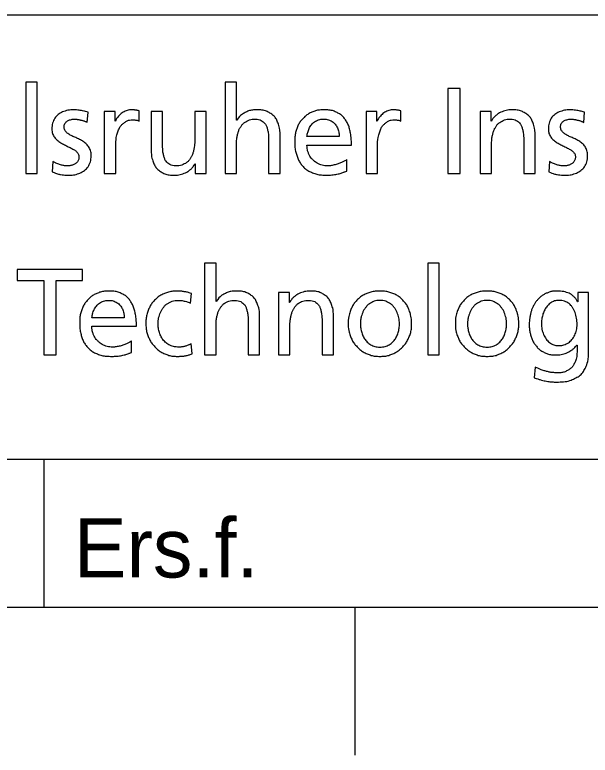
# Model space of a CAD drawing. Extents: x 0 to 395, y 0 to 270.
# Drawn here: x 136.01 to 155.45, y 0 to 25 of the extents above; entities that cross this region are included whole.
import ezdxf

# ---------------------------------------------------------------- set-up
doc = ezdxf.new("R2010")
doc.units = 0
doc.layers.add('90_Plankopf', color=7, linetype='Continuous')

msp = doc.modelspace()

# ---------------------------------------------------------------- linework, layer by layer
at = {"layer": '90_Plankopf'}
for p, q in [((5, 25), (390, 25)), ((140.21, 21.414), (140.21, 21.761)), ((149.056, 21.414), (149.056, 21.761)), ((138.456, 21.369), (138.489, 21.708)), ((155.231, 21.369), (155.264, 21.708)), ((146.971, 20.89), (145.882, 20.89)), ((145.882, 20.602), (147.384, 20.602)), ((137.296, 20.048), (137.276, 19.702)), ((147.223, 19.723), (147.223, 20.11)), ((154.071, 20.048), (154.051, 19.702)), ((141.95, 15.266), (141.983, 15.588)), ((139.705, 14.771), (138.615, 14.771)), ((138.615, 14.482), (140.118, 14.482)), ((139.957, 13.603), (139.957, 13.991)), ((142, 13.553), (141.971, 13.9)), ((153.595, 13.104), (153.554, 12.745)), ((100, 10), (225, 10)), ((137, 5), (137, 10)), ((5, 5), (390, 5)), ((147.5, 5), (147.5, 0))]:
    msp.add_line(p, q, dxfattribs=at)
for points in [[(136.38, 19.636), (136.767, 19.636), (136.767, 22.731), (136.38, 22.731), (136.38, 19.636)], [(143.508, 21.439), (143.5, 21.439), (143.5, 22.731), (143.112, 22.731), (143.112, 19.636), (143.5, 19.636), (143.5, 20.61)], [(150.645, 19.636), (151.058, 19.636), (151.058, 22.516), (150.645, 22.516), (150.645, 19.636)], [(139.406, 21.414), (139.397, 21.414), (139.397, 21.74), (139.034, 21.74), (139.034, 19.636), (139.422, 19.636), (139.422, 20.593)], [(141.003, 20.651), (141.003, 21.74), (140.615, 21.74), (140.615, 20.49)], [(142.092, 19.97), (142.101, 19.97), (142.101, 19.636), (142.476, 19.636), (142.476, 21.74), (142.088, 21.74), (142.088, 20.766)], [(148.251, 21.414), (148.243, 21.414), (148.243, 21.74), (147.88, 21.74), (147.88, 19.636), (148.268, 19.636), (148.268, 20.593)], [(152.115, 21.406), (152.107, 21.406), (152.107, 21.74), (151.731, 21.74), (151.731, 19.636), (152.119, 19.636), (152.119, 20.61)], [(144.586, 20.725), (144.586, 19.636), (144.973, 19.636), (144.973, 20.886)], [(153.204, 20.725), (153.204, 19.636), (153.592, 19.636), (153.592, 20.886)], [(142.817, 15.32), (142.809, 15.32), (142.809, 16.611), (142.421, 16.611), (142.421, 13.516), (142.809, 13.516), (142.809, 14.49)], [(149.962, 13.516), (150.35, 13.516), (150.35, 16.611), (149.962, 16.611), (149.962, 13.516)], [(136.989, 13.516), (137.402, 13.516), (137.402, 16.034), (138.297, 16.034), (138.297, 16.397), (136.093, 16.397), (136.093, 16.034), (136.989, 16.034), (136.989, 13.516)], [(145.302, 15.287), (145.294, 15.287), (145.294, 15.621), (144.918, 15.621), (144.918, 13.516), (145.306, 13.516), (145.306, 14.49)], [(155.394, 13.607), (155.394, 15.621), (155.035, 15.621), (155.035, 15.308), (155.027, 15.308)], [(143.894, 14.606), (143.894, 13.516), (144.282, 13.516), (144.282, 14.767)], [(146.392, 14.606), (146.392, 13.516), (146.779, 13.516), (146.779, 14.767)], [(154.998, 13.842), (155.006, 13.842), (155.006, 13.636)]]:
    msp.add_lwpolyline(points, dxfattribs=at)
for points in [[(138.489, 21.708), (138.413, 21.731), (138.336, 21.75), (138.258, 21.766), (138.18, 21.781), (138.096, 21.789), (138.006, 21.79), (137.902, 21.79), (137.804, 21.777), (137.715, 21.75), (137.624, 21.724), (137.546, 21.683), (137.479, 21.63), (137.411, 21.577), (137.358, 21.509), (137.321, 21.428), (137.283, 21.347), (137.264, 21.251), (137.263, 21.142), (137.264, 21.058), (137.281, 20.986), (137.314, 20.924), (137.346, 20.863), (137.39, 20.81), (137.444, 20.764), (137.499, 20.72), (137.558, 20.68), (137.622, 20.645), (137.687, 20.61), (137.752, 20.577), (137.816, 20.547), (137.881, 20.516), (137.941, 20.485), (137.994, 20.452), (138.049, 20.42), (138.092, 20.384), (138.125, 20.343), (138.157, 20.303), (138.175, 20.255), (138.175, 20.201), (138.175, 20.145), (138.162, 20.097), (138.138, 20.058), (138.115, 20.02), (138.083, 19.989), (138.044, 19.965), (138.005, 19.942), (137.962, 19.925), (137.916, 19.915), (137.87, 19.905), (137.824, 19.9), (137.779, 19.9), (137.741, 19.9), (137.694, 19.905), (137.638, 19.916), (137.583, 19.927), (137.525, 19.944), (137.465, 19.966), (137.404, 19.988), (137.349, 20.015), (137.296, 20.048)], [(140.21, 21.761), (140.183, 21.767), (140.157, 21.771), (140.133, 21.776), (140.109, 21.78), (140.082, 21.784), (140.053, 21.786), (140.025, 21.789), (139.992, 21.79), (139.954, 21.79), (139.879, 21.789), (139.807, 21.773), (139.736, 21.741), (139.666, 21.709), (139.602, 21.666), (139.545, 21.609), (139.487, 21.553), (139.441, 21.488), (139.406, 21.414)], [(144.973, 20.886), (144.974, 21.075), (144.946, 21.237), (144.89, 21.372), (144.835, 21.507), (144.748, 21.61), (144.632, 21.681), (144.515, 21.753), (144.367, 21.789), (144.185, 21.79), (144.037, 21.789), (143.906, 21.759), (143.79, 21.698), (143.674, 21.638), (143.58, 21.551), (143.508, 21.439)], [(147.384, 20.602), (147.385, 20.771), (147.369, 20.929), (147.338, 21.073), (147.306, 21.217), (147.255, 21.342), (147.183, 21.449), (147.111, 21.557), (147.016, 21.64), (146.897, 21.699), (146.778, 21.759), (146.63, 21.789), (146.456, 21.79), (146.306, 21.789), (146.172, 21.763), (146.05, 21.712), (145.93, 21.659), (145.826, 21.586), (145.74, 21.491), (145.653, 21.397), (145.586, 21.285), (145.54, 21.154), (145.493, 21.025), (145.47, 20.882), (145.469, 20.725), (145.469, 20.553), (145.491, 20.398), (145.535, 20.258), (145.578, 20.118), (145.645, 19.999), (145.734, 19.899), (145.824, 19.799), (145.936, 19.722), (146.073, 19.668), (146.211, 19.614), (146.372, 19.587), (146.559, 19.586), (146.674, 19.587), (146.771, 19.595), (146.852, 19.61), (146.933, 19.625), (147.003, 19.643), (147.062, 19.663), (147.121, 19.684), (147.174, 19.704), (147.223, 19.723)], [(149.056, 21.761), (149.029, 21.767), (149.003, 21.771), (148.979, 21.776), (148.954, 21.78), (148.927, 21.784), (148.899, 21.786), (148.871, 21.789), (148.838, 21.79), (148.8, 21.79), (148.725, 21.789), (148.652, 21.773), (148.581, 21.741), (148.511, 21.709), (148.447, 21.666), (148.39, 21.609), (148.332, 21.553), (148.286, 21.488), (148.251, 21.414)], [(153.592, 20.886), (153.593, 21.075), (153.565, 21.237), (153.509, 21.372), (153.453, 21.507), (153.367, 21.61), (153.25, 21.681), (153.134, 21.753), (152.985, 21.789), (152.804, 21.79), (152.706, 21.79), (152.611, 21.774), (152.521, 21.744), (152.43, 21.713), (152.35, 21.67), (152.28, 21.612), (152.209, 21.555), (152.154, 21.487), (152.115, 21.406)], [(155.264, 21.708), (155.188, 21.731), (155.111, 21.75), (155.034, 21.766), (154.955, 21.781), (154.871, 21.789), (154.781, 21.79), (154.677, 21.79), (154.579, 21.777), (154.49, 21.75), (154.4, 21.724), (154.321, 21.683), (154.254, 21.63), (154.186, 21.577), (154.133, 21.509), (154.096, 21.428), (154.058, 21.347), (154.039, 21.251), (154.038, 21.142), (154.039, 21.058), (154.056, 20.986), (154.089, 20.924), (154.122, 20.863), (154.165, 20.81), (154.219, 20.764), (154.274, 20.72), (154.333, 20.68), (154.397, 20.645), (154.462, 20.61), (154.527, 20.577), (154.592, 20.547), (154.656, 20.516), (154.716, 20.485), (154.769, 20.452), (154.824, 20.42), (154.867, 20.384), (154.9, 20.343), (154.932, 20.303), (154.95, 20.255), (154.95, 20.201), (154.95, 20.145), (154.937, 20.097), (154.913, 20.058), (154.89, 20.02), (154.858, 19.989), (154.819, 19.965), (154.78, 19.942), (154.737, 19.925), (154.691, 19.915), (154.645, 19.905), (154.599, 19.9), (154.554, 19.9), (154.516, 19.9), (154.469, 19.905), (154.413, 19.916), (154.358, 19.927), (154.3, 19.944), (154.24, 19.966), (154.179, 19.988), (154.124, 20.015), (154.071, 20.048)], [(137.276, 19.702), (137.365, 19.656), (137.459, 19.624), (137.557, 19.608), (137.655, 19.592), (137.754, 19.585), (137.853, 19.586), (137.948, 19.586), (138.039, 19.599), (138.126, 19.625), (138.214, 19.652), (138.292, 19.692), (138.362, 19.746), (138.43, 19.799), (138.486, 19.868), (138.526, 19.95), (138.567, 20.033), (138.587, 20.13), (138.588, 20.242), (138.587, 20.338), (138.57, 20.419), (138.538, 20.486), (138.505, 20.552), (138.461, 20.609), (138.407, 20.656), (138.353, 20.702), (138.294, 20.741), (138.229, 20.775), (138.164, 20.808), (138.1, 20.839), (138.035, 20.867), (137.97, 20.896), (137.911, 20.925), (137.857, 20.956), (137.803, 20.988), (137.759, 21.025), (137.726, 21.066), (137.694, 21.109), (137.677, 21.16), (137.676, 21.221), (137.677, 21.278), (137.695, 21.326), (137.728, 21.364), (137.762, 21.402), (137.807, 21.43), (137.863, 21.449), (137.919, 21.468), (137.981, 21.476), (138.047, 21.476), (138.071, 21.476), (138.101, 21.473), (138.138, 21.468), (138.174, 21.461), (138.212, 21.453), (138.253, 21.443), (138.294, 21.433), (138.332, 21.421), (138.368, 21.408), (138.404, 21.396), (138.433, 21.383), (138.456, 21.369)], [(139.422, 20.593), (139.423, 20.77), (139.447, 20.923), (139.494, 21.051), (139.541, 21.179), (139.607, 21.278), (139.693, 21.346), (139.778, 21.416), (139.879, 21.451), (139.996, 21.451), (140.029, 21.452), (140.064, 21.449), (140.102, 21.444), (140.139, 21.439), (140.174, 21.429), (140.21, 21.414)], [(143.5, 20.61), (143.5, 20.738), (143.513, 20.855), (143.538, 20.961), (143.564, 21.067), (143.602, 21.158), (143.654, 21.235), (143.707, 21.312), (143.773, 21.371), (143.854, 21.413), (143.934, 21.455), (144.03, 21.476), (144.14, 21.476), (144.252, 21.47), (144.341, 21.439), (144.406, 21.381), (144.472, 21.325), (144.518, 21.242), (144.545, 21.134), (144.573, 21.025), (144.586, 20.889), (144.586, 20.725)], [(145.882, 20.89), (145.889, 20.959), (145.905, 21.028), (145.929, 21.097), (145.953, 21.165), (145.988, 21.228), (146.033, 21.286), (146.078, 21.343), (146.134, 21.388), (146.203, 21.423), (146.271, 21.458), (146.352, 21.476), (146.447, 21.476), (146.531, 21.476), (146.605, 21.46), (146.67, 21.43), (146.736, 21.4), (146.79, 21.358), (146.835, 21.304), (146.879, 21.251), (146.914, 21.188), (146.936, 21.118), (146.96, 21.047), (146.971, 20.972), (146.971, 20.89)], [(148.268, 20.593), (148.268, 20.77), (148.292, 20.923), (148.339, 21.051), (148.387, 21.179), (148.453, 21.278), (148.539, 21.346), (148.624, 21.416), (148.725, 21.451), (148.841, 21.451), (148.875, 21.452), (148.91, 21.449), (148.947, 21.444), (148.984, 21.439), (149.02, 21.429), (149.056, 21.414)], [(152.119, 20.61), (152.119, 20.738), (152.131, 20.855), (152.157, 20.961), (152.182, 21.067), (152.221, 21.158), (152.273, 21.235), (152.325, 21.312), (152.392, 21.371), (152.472, 21.413), (152.553, 21.455), (152.649, 21.476), (152.759, 21.476), (152.871, 21.47), (152.959, 21.439), (153.025, 21.381), (153.09, 21.325), (153.136, 21.242), (153.164, 21.134), (153.192, 21.025), (153.205, 20.889), (153.204, 20.725)], [(154.051, 19.702), (154.14, 19.656), (154.234, 19.624), (154.332, 19.608), (154.43, 19.592), (154.529, 19.585), (154.629, 19.586), (154.724, 19.586), (154.814, 19.599), (154.901, 19.625), (154.989, 19.652), (155.067, 19.692), (155.137, 19.746), (155.206, 19.799), (155.261, 19.868), (155.301, 19.95), (155.342, 20.033), (155.362, 20.13), (155.363, 20.242), (155.362, 20.338), (155.345, 20.419), (155.313, 20.486), (155.28, 20.552), (155.236, 20.609), (155.182, 20.656), (155.128, 20.702), (155.069, 20.741), (155.004, 20.775), (154.939, 20.808), (154.875, 20.839), (154.81, 20.867), (154.745, 20.896), (154.686, 20.925), (154.632, 20.956), (154.578, 20.988), (154.534, 21.025), (154.501, 21.066), (154.469, 21.109), (154.452, 21.16), (154.451, 21.221), (154.452, 21.278), (154.47, 21.326), (154.503, 21.364), (154.537, 21.402), (154.582, 21.43), (154.638, 21.449), (154.694, 21.468), (154.756, 21.476), (154.822, 21.476), (154.846, 21.476), (154.876, 21.473), (154.913, 21.468), (154.949, 21.461), (154.988, 21.453), (155.028, 21.443), (155.069, 21.433), (155.107, 21.421), (155.144, 21.408), (155.179, 21.396), (155.208, 21.383), (155.231, 21.369)], [(142.088, 20.766), (142.088, 20.638), (142.076, 20.521), (142.05, 20.415), (142.025, 20.309), (141.987, 20.218), (141.934, 20.141), (141.882, 20.064), (141.815, 20.005), (141.735, 19.963), (141.654, 19.921), (141.559, 19.9), (141.449, 19.9), (141.337, 19.907), (141.248, 19.938), (141.183, 19.995), (141.117, 20.051), (141.071, 20.134), (141.044, 20.242), (141.015, 20.351), (141.002, 20.487), (141.003, 20.651)], [(147.223, 20.11), (147.199, 20.09), (147.164, 20.068), (147.118, 20.044), (147.072, 20.02), (147.02, 19.998), (146.96, 19.975), (146.9, 19.953), (146.837, 19.936), (146.771, 19.922), (146.705, 19.908), (146.64, 19.9), (146.575, 19.9), (146.482, 19.9), (146.395, 19.917), (146.312, 19.951), (146.229, 19.984), (146.155, 20.033), (146.091, 20.095), (146.026, 20.157), (145.975, 20.23), (145.938, 20.316), (145.902, 20.402), (145.883, 20.497), (145.882, 20.602)], [(140.615, 20.49), (140.615, 20.301), (140.643, 20.139), (140.698, 20.004), (140.754, 19.869), (140.841, 19.766), (140.957, 19.695), (141.073, 19.623), (141.223, 19.587), (141.403, 19.586), (141.502, 19.587), (141.597, 19.602), (141.687, 19.632), (141.777, 19.663), (141.857, 19.707), (141.928, 19.764), (141.998, 19.821), (142.053, 19.89), (142.092, 19.97)], [(140.118, 14.482), (140.118, 14.652), (140.102, 14.81), (140.071, 14.953), (140.04, 15.098), (139.988, 15.223), (139.917, 15.33), (139.845, 15.437), (139.75, 15.521), (139.63, 15.58), (139.511, 15.639), (139.364, 15.67), (139.189, 15.67), (139.04, 15.67), (138.905, 15.644), (138.784, 15.592), (138.664, 15.54), (138.56, 15.467), (138.473, 15.372), (138.386, 15.277), (138.32, 15.165), (138.274, 15.035), (138.227, 14.906), (138.204, 14.763), (138.203, 14.606), (138.203, 14.434), (138.224, 14.278), (138.268, 14.139), (138.311, 13.999), (138.378, 13.88), (138.468, 13.78), (138.557, 13.679), (138.67, 13.602), (138.807, 13.549), (138.944, 13.494), (139.106, 13.468), (139.292, 13.467), (139.407, 13.468), (139.505, 13.475), (139.586, 13.49), (139.666, 13.505), (139.736, 13.523), (139.796, 13.544), (139.854, 13.564), (139.908, 13.584), (139.957, 13.603)], [(141.983, 15.588), (141.945, 15.603), (141.9, 15.617), (141.847, 15.63), (141.794, 15.642), (141.738, 15.652), (141.68, 15.659), (141.621, 15.667), (141.566, 15.67), (141.513, 15.67), (141.351, 15.67), (141.205, 15.642), (141.073, 15.589), (140.942, 15.535), (140.829, 15.458), (140.735, 15.36), (140.641, 15.261), (140.568, 15.145), (140.517, 15.011), (140.466, 14.877), (140.441, 14.73), (140.44, 14.569), (140.441, 14.418), (140.467, 14.275), (140.518, 14.142), (140.57, 14.009), (140.643, 13.893), (140.738, 13.792), (140.833, 13.691), (140.946, 13.611), (141.077, 13.554), (141.208, 13.497), (141.353, 13.468), (141.513, 13.467), (141.56, 13.467), (141.611, 13.469), (141.666, 13.473), (141.721, 13.477), (141.776, 13.485), (141.833, 13.498), (141.89, 13.511), (141.945, 13.529), (142, 13.553)], [(144.282, 14.767), (144.283, 14.956), (144.255, 15.118), (144.199, 15.253), (144.143, 15.387), (144.057, 15.49), (143.941, 15.562), (143.824, 15.634), (143.676, 15.67), (143.494, 15.67), (143.346, 15.67), (143.215, 15.639), (143.099, 15.579), (142.982, 15.519), (142.889, 15.432), (142.817, 15.32)], [(146.779, 14.767), (146.78, 14.956), (146.752, 15.118), (146.696, 15.253), (146.641, 15.387), (146.554, 15.49), (146.438, 15.562), (146.322, 15.634), (146.173, 15.67), (145.991, 15.67), (145.893, 15.67), (145.798, 15.655), (145.708, 15.625), (145.618, 15.594), (145.537, 15.55), (145.467, 15.492), (145.397, 15.435), (145.341, 15.367), (145.302, 15.287)], [(149.394, 14.821), (149.381, 14.887), (149.363, 14.95), (149.34, 15.011), (149.289, 15.145), (149.217, 15.261), (149.123, 15.36), (149.028, 15.458), (148.916, 15.535), (148.785, 15.589), (148.654, 15.642), (148.509, 15.67), (148.348, 15.67), (148.187, 15.67), (148.04, 15.642), (147.909, 15.589), (147.777, 15.535), (147.665, 15.458), (147.57, 15.36), (147.476, 15.261), (147.403, 15.145), (147.352, 15.011), (147.301, 14.877), (147.276, 14.73), (147.275, 14.569)], [(153.014, 14.821), (153.001, 14.887), (152.983, 14.95), (152.96, 15.011), (152.909, 15.145), (152.837, 15.261), (152.743, 15.36), (152.649, 15.458), (152.536, 15.535), (152.405, 15.589), (152.274, 15.642), (152.129, 15.67), (151.969, 15.67), (151.807, 15.67), (151.66, 15.642), (151.529, 15.589), (151.398, 15.535), (151.285, 15.458), (151.191, 15.36), (151.096, 15.261), (151.023, 15.145), (150.972, 15.011), (150.922, 14.877), (150.896, 14.73), (150.896, 14.569)], [(155.027, 15.308), (154.989, 15.384), (154.94, 15.448), (154.878, 15.503), (154.817, 15.556), (154.742, 15.598), (154.653, 15.627), (154.563, 15.656), (154.456, 15.67), (154.333, 15.67), (154.206, 15.67), (154.093, 15.648), (153.992, 15.606), (153.891, 15.564), (153.803, 15.506), (153.728, 15.432), (153.652, 15.359), (153.591, 15.274), (153.541, 15.18), (153.491, 15.085), (153.454, 14.983), (153.43, 14.876), (153.405, 14.769), (153.393, 14.661), (153.393, 14.552), (153.393, 14.415), (153.411, 14.285), (153.449, 14.161), (153.486, 14.037), (153.542, 13.926), (153.617, 13.83), (153.691, 13.734), (153.785, 13.657), (153.898, 13.602), (154.01, 13.546), (154.142, 13.518), (154.293, 13.516), (154.382, 13.516), (154.471, 13.528), (154.558, 13.552), (154.645, 13.576), (154.726, 13.613), (154.801, 13.661), (154.877, 13.709), (154.942, 13.77), (154.998, 13.842)], [(138.615, 14.771), (138.622, 14.84), (138.638, 14.908), (138.663, 14.977), (138.687, 15.046), (138.721, 15.109), (138.767, 15.166), (138.811, 15.224), (138.868, 15.269), (138.936, 15.304), (139.005, 15.338), (139.086, 15.356), (139.181, 15.357), (139.265, 15.356), (139.339, 15.341), (139.403, 15.311), (139.469, 15.28), (139.523, 15.239), (139.568, 15.185), (139.613, 15.131), (139.647, 15.069), (139.67, 14.999), (139.693, 14.928), (139.705, 14.852), (139.705, 14.771)], [(141.971, 13.9), (141.931, 13.874), (141.886, 13.852), (141.839, 13.834), (141.792, 13.816), (141.743, 13.803), (141.694, 13.794), (141.646, 13.785), (141.599, 13.78), (141.554, 13.78), (141.455, 13.781), (141.366, 13.796), (141.289, 13.827), (141.213, 13.856), (141.147, 13.897), (141.091, 13.95), (141.036, 14.002), (140.991, 14.062), (140.956, 14.129), (140.92, 14.197), (140.895, 14.267), (140.877, 14.342), (140.861, 14.418), (140.853, 14.493), (140.853, 14.569), (140.853, 14.67), (140.867, 14.768), (140.897, 14.861), (140.927, 14.955), (140.971, 15.039), (141.029, 15.113), (141.086, 15.188), (141.156, 15.247), (141.24, 15.29), (141.324, 15.333), (141.421, 15.356), (141.529, 15.357), (141.592, 15.357), (141.659, 15.35), (141.73, 15.335), (141.802, 15.32), (141.875, 15.297), (141.95, 15.266)], [(142.809, 14.49), (142.809, 14.619), (142.822, 14.736), (142.847, 14.842), (142.872, 14.948), (142.911, 15.039), (142.963, 15.115), (143.015, 15.193), (143.082, 15.252), (143.163, 15.294), (143.243, 15.336), (143.339, 15.356), (143.449, 15.357), (143.561, 15.35), (143.65, 15.319), (143.715, 15.262), (143.78, 15.206), (143.826, 15.123), (143.854, 15.014), (143.882, 14.906), (143.895, 14.77), (143.894, 14.606)], [(145.306, 14.49), (145.306, 14.619), (145.319, 14.736), (145.344, 14.842), (145.37, 14.948), (145.408, 15.039), (145.46, 15.115), (145.513, 15.193), (145.579, 15.252), (145.66, 15.294), (145.74, 15.336), (145.836, 15.356), (145.946, 15.357), (146.058, 15.35), (146.147, 15.319), (146.212, 15.262), (146.277, 15.206), (146.324, 15.123), (146.351, 15.014), (146.379, 14.906), (146.392, 14.77), (146.392, 14.606)], [(147.688, 14.569), (147.688, 14.67), (147.703, 14.768), (147.733, 14.861), (147.762, 14.955), (147.805, 15.039), (147.862, 15.113), (147.918, 15.188), (147.988, 15.247), (148.069, 15.29), (148.151, 15.333), (148.244, 15.356), (148.348, 15.357), (148.451, 15.356), (148.543, 15.333), (148.625, 15.29), (148.706, 15.247), (148.775, 15.188), (148.831, 15.113), (148.887, 15.039), (148.931, 14.955), (148.96, 14.861), (148.989, 14.768), (149.004, 14.67), (149.004, 14.569), (149.004, 14.493), (148.996, 14.418), (148.98, 14.342), (148.963, 14.267), (148.938, 14.197), (148.904, 14.129), (148.87, 14.062), (148.828, 14.002), (148.775, 13.95), (148.723, 13.897), (148.662, 13.856), (148.591, 13.827), (148.52, 13.796), (148.439, 13.781), (148.348, 13.78), (148.257, 13.781), (148.175, 13.796), (148.103, 13.827), (148.032, 13.856), (147.97, 13.897), (147.918, 13.95), (147.865, 14.002), (147.823, 14.062), (147.789, 14.129), (147.755, 14.197), (147.729, 14.267), (147.713, 14.342), (147.696, 14.418), (147.688, 14.493), (147.688, 14.569)], [(151.308, 14.569), (151.308, 14.67), (151.323, 14.768), (151.353, 14.861), (151.382, 14.955), (151.425, 15.039), (151.482, 15.113), (151.539, 15.188), (151.608, 15.247), (151.689, 15.29), (151.771, 15.333), (151.864, 15.356), (151.969, 15.357), (152.072, 15.356), (152.164, 15.333), (152.245, 15.29), (152.326, 15.247), (152.395, 15.188), (152.451, 15.113), (152.508, 15.039), (152.551, 14.955), (152.58, 14.861), (152.61, 14.768), (152.624, 14.67), (152.624, 14.569), (152.624, 14.493), (152.616, 14.418), (152.6, 14.342), (152.583, 14.267), (152.559, 14.197), (152.524, 14.129), (152.491, 14.062), (152.448, 14.002), (152.395, 13.95), (152.344, 13.897), (152.282, 13.856), (152.211, 13.827), (152.14, 13.796), (152.059, 13.781), (151.969, 13.78), (151.877, 13.781), (151.795, 13.796), (151.724, 13.827), (151.652, 13.856), (151.59, 13.897), (151.538, 13.95), (151.486, 14.002), (151.443, 14.062), (151.409, 14.129), (151.375, 14.197), (151.35, 14.267), (151.333, 14.342), (151.316, 14.418), (151.308, 14.493), (151.308, 14.569)], [(154.391, 13.83), (154.301, 13.831), (154.219, 13.851), (154.147, 13.891), (154.074, 13.93), (154.013, 13.984), (153.962, 14.053), (153.911, 14.122), (153.873, 14.201), (153.846, 14.289), (153.819, 14.379), (153.805, 14.473), (153.805, 14.573), (153.805, 14.645), (153.813, 14.718), (153.829, 14.792), (153.844, 14.866), (153.867, 14.937), (153.899, 15.004), (153.93, 15.071), (153.969, 15.131), (154.016, 15.184), (154.063, 15.237), (154.118, 15.279), (154.18, 15.31), (154.243, 15.34), (154.313, 15.356), (154.391, 15.357), (154.495, 15.356), (154.585, 15.334), (154.662, 15.292), (154.739, 15.249), (154.803, 15.19), (154.854, 15.115), (154.904, 15.039), (154.943, 14.953), (154.968, 14.855), (154.994, 14.758), (155.006, 14.654), (155.006, 14.544), (155.006, 14.446), (154.991, 14.353), (154.962, 14.267), (154.932, 14.181), (154.889, 14.105), (154.835, 14.04), (154.781, 13.975), (154.716, 13.924), (154.641, 13.886), (154.565, 13.849), (154.483, 13.831), (154.391, 13.83)], [(147.275, 14.569), (147.276, 14.418), (147.302, 14.275), (147.354, 14.142), (147.405, 14.009), (147.478, 13.893), (147.574, 13.792), (147.669, 13.691), (147.781, 13.611), (147.912, 13.554), (148.044, 13.497), (148.189, 13.468), (148.348, 13.467), (148.506, 13.468), (148.652, 13.497), (148.781, 13.554), (148.912, 13.611), (149.025, 13.691), (149.119, 13.792), (149.214, 13.893), (149.287, 14.009), (149.339, 14.142), (149.39, 14.275), (149.416, 14.418), (149.417, 14.569), (149.417, 14.657), (149.409, 14.741), (149.394, 14.821)], [(150.896, 14.569), (150.896, 14.418), (150.922, 14.275), (150.974, 14.142), (151.025, 14.009), (151.098, 13.893), (151.194, 13.792), (151.289, 13.691), (151.402, 13.611), (151.532, 13.554), (151.664, 13.497), (151.809, 13.468), (151.969, 13.467), (152.127, 13.468), (152.272, 13.497), (152.402, 13.554), (152.532, 13.611), (152.645, 13.691), (152.739, 13.792), (152.834, 13.893), (152.907, 14.009), (152.959, 14.142), (153.011, 14.275), (153.036, 14.418), (153.037, 14.569), (153.037, 14.657), (153.029, 14.741), (153.014, 14.821)], [(139.957, 13.991), (139.932, 13.971), (139.898, 13.949), (139.851, 13.925), (139.805, 13.901), (139.753, 13.878), (139.693, 13.856), (139.633, 13.834), (139.571, 13.816), (139.505, 13.802), (139.439, 13.788), (139.373, 13.781), (139.308, 13.78), (139.216, 13.781), (139.129, 13.798), (139.045, 13.832), (138.963, 13.865), (138.888, 13.913), (138.824, 13.975), (138.76, 14.037), (138.709, 14.111), (138.672, 14.197), (138.635, 14.283), (138.616, 14.378), (138.615, 14.482)], [(153.554, 12.745), (153.665, 12.707), (153.764, 12.676), (153.85, 12.656), (153.936, 12.634), (154.016, 12.62), (154.089, 12.612), (154.162, 12.603), (154.236, 12.6), (154.309, 12.6), (154.56, 12.601), (154.766, 12.64), (154.926, 12.719), (155.086, 12.798), (155.204, 12.912), (155.281, 13.062), (155.357, 13.212), (155.395, 13.393), (155.394, 13.607)], [(155.006, 13.636), (155.005, 13.487), (154.98, 13.358), (154.928, 13.251), (154.876, 13.143), (154.802, 13.06), (154.705, 13.002), (154.608, 12.944), (154.491, 12.914), (154.354, 12.914), (154.283, 12.914), (154.218, 12.917), (154.157, 12.924), (154.096, 12.931), (154.037, 12.943), (153.979, 12.958), (153.921, 12.973), (153.861, 12.992), (153.799, 13.016), (153.736, 13.04), (153.669, 13.07), (153.595, 13.104)]]:
    msp.add_open_spline(points, degree=3, dxfattribs=at)

# ---------------------------------------------------------------- texts
msp.add_text('Ers.f.', height=2, dxfattribs=at).set_placement((138, 6))

doc.saveas('drawing.dxf')
